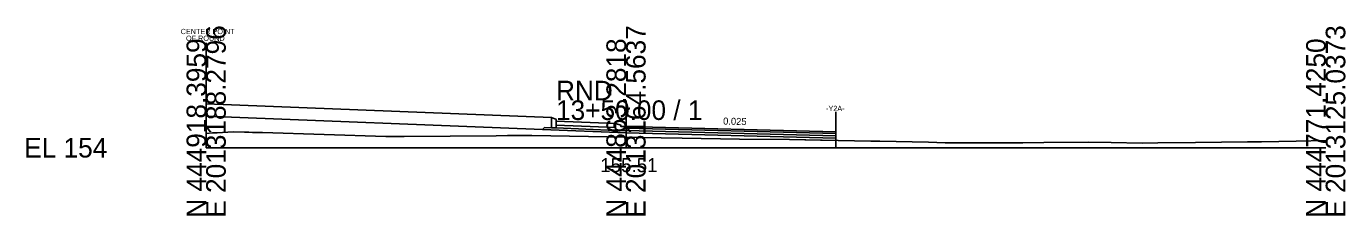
# Model space of a CAD drawing. Extents: x -26 to 163, y -10 to 7518.
# Drawn here: x -25.7 to 162.8, y 6990.3 to 7017.3 of the extents above; entities that cross this region are included whole.
import ezdxf

# ---------------------------------------------------------------- set-up
doc = ezdxf.new("R2010")
doc.units = 0
for name, color, linetype in [('Exist Cross Section Cell', 7, 'Continuous'), ('Exist XS Center Line Elevation Label', 7, 'Continuous'), ('Exist XS Ground Line', 7, 'Continuous'), ('Prop CMT Conc Surface', 7, 'Continuous'), ('Prop CMT Concrete Structures', 7, 'Continuous'), ('Prop CMT Pvmt Course 1', 7, 'Continuous'), ('Prop CMT Pvmt Course 1 CG', 7, 'Continuous'), ('Prop CMT Pvmt Course 2', 7, 'Continuous'), ('Prop CMT Pvmt Course 3', 7, 'Continuous'), ('Prop CMT Pvmt Surface', 7, 'Continuous'), ('Prop CMT Shear Line', 7, 'Continuous'), ('Prop CMT Shear Line Text', 7, 'Continuous'), ('Prop CMT Slope Grass', 7, 'Continuous'), ('Prop CMT Subgrade Earthwork', 7, 'Continuous'), ('Prop XS Earthwork Shape', 7, 'Continuous'), ('Prop XS SE Text', 7, 'Continuous')]:
    doc.layers.add(name, color=color, linetype=linetype)

msp = doc.modelspace()

# ---------------------------------------------------------------- linework, layer by layer
at = {"layer": 'Exist Cross Section Cell'}
for p, q in [((60, 7000), (60, 7006.76)), ((0, 7000), (60, 7000)), ((60, 7000), (160, 7000))]:
    msp.add_line(p, q, dxfattribs=at)
at = {"layer": 'Exist XS Ground Line'}
msp.add_lwpolyline([(0, 7002.05), (0.89, 7002.1), (1.57, 7002.14), (3.85, 7002.25), (5.5, 7002.24), (6.12, 7002.21), (6.63, 7002.19), (7.29, 7002.17), (8.04, 7002.16), (25.69, 7001.61), (26.99, 7001.59), (28.32, 7001.59), (41.46, 7001.71), (43.05, 7001.72), (44.03, 7001.72), (46.53, 7001.73), (60, 7001.51), (62.02, 7001.48), (68.01, 7001.37), (76.24, 7001.24), (83.36, 7001.15), (95.01, 7000.95), (96.27, 7000.92), (103.21, 7000.77), (105.6, 7000.71), (107.14, 7000.68), (111.08, 7000.68), (116.72, 7000.68), (119.69, 7000.72), (126.06, 7000.79), (129.33, 7000.74), (133.77, 7000.66), (136.02, 7000.68), (141.4, 7000.74), (148.82, 7000.83), (150.82, 7000.85), (155.79, 7000.93), (160, 7001.03)], dxfattribs=at)
at = {"layer": 'Prop CMT Conc Surface'}
for points in [[(50, 7003.99), (49.96, 7004.09), (49.85, 7004.14), (49.34, 7004.33)], [(50, 7003.83), (50, 7003.99)], [(60, 7003.03), (59.25, 7003.05), (59.25, 7003.22), (58.5, 7003.47)]]:
    msp.add_lwpolyline(points, dxfattribs=at)
at = {"layer": 'Prop CMT Concrete Structures'}
for points in [[(50, 7003.99), (49.96, 7004.09), (49.85, 7004.14), (49.34, 7004.33)], [(49.34, 7004.33), (49.34, 7002.83)], [(50, 7003.83), (50, 7003.99)], [(49.34, 7002.83), (50, 7002.83)], [(50, 7002.83), (50, 7003.83)], [(50, 7003.83), (50, 7003.24)], [(58.5, 7003.47), (50, 7003.81)], [(50, 7003.22), (58.5, 7002.88)], [(60, 7003.03), (59.25, 7003.05), (59.25, 7003.22), (58.5, 7003.47)], [(58.5, 7003.47), (58.5, 7002.48)], [(58.5, 7002.88), (58.5, 7003.47)], [(58.5, 7002.48), (60, 7002.45)], [(60, 7002.45), (60, 7003.03)]]:
    msp.add_lwpolyline(points, dxfattribs=at)
at = {"layer": 'Prop CMT Pvmt Course 1'}
for points in [[(60, 7003.03), (90, 7002.28)], [(60, 7002.78), (60, 7003.03)], [(90, 7002.03), (60, 7002.78)], [(90, 7002.28), (90, 7002.03)]]:
    msp.add_lwpolyline(points, dxfattribs=at)
msp.add_lwpolyline([(60, 7002.78), (60, 7002.9), (60, 7002.9), (60, 7002.78)], close=True, dxfattribs=at)
at = {"layer": 'Prop CMT Pvmt Course 1 CG'}
for points in [[(60, 7002.11), (60, 7002.45)], [(90, 7001.36), (90, 7001.69)]]:
    msp.add_lwpolyline(points, dxfattribs=at)
at = {"layer": 'Prop CMT Pvmt Course 2'}
for points in [[(60, 7002.45), (60, 7002.78)], [(60, 7002.78), (90, 7002.03)], [(90, 7001.69), (60, 7002.45)], [(90, 7002.03), (90, 7001.69)]]:
    msp.add_lwpolyline(points, dxfattribs=at)
at = {"layer": 'Prop CMT Pvmt Course 3'}
for points in [[(50, 7002.83), (58.5, 7002.48)], [(60, 7002.45), (90, 7001.69)], [(60, 7002.11), (60, 7002.45)], [(90, 7001.36), (60, 7002.11)], [(90, 7001.69), (90, 7001.36)]]:
    msp.add_lwpolyline(points, dxfattribs=at)
at = {"layer": 'Prop CMT Pvmt Surface'}
msp.add_lwpolyline([(60, 7003.03), (90, 7002.28)], dxfattribs=at)
at = {"layer": 'Prop CMT Shear Line'}
for p, q in [((0, 6999.97), (0, 7014.97)), ((90, 7000.1), (90, 7005.12))]:
    msp.add_line(p, q, dxfattribs=at)
at = {"layer": 'Prop CMT Slope Grass'}
for p, q in [((49.34, 7004.31), (0, 7006.28)), ((48.06, 7002.59), (0, 7004.51))]:
    msp.add_line(p, q, dxfattribs=at)
at = {"layer": 'Prop CMT Subgrade Earthwork'}
for p, q in [((0, 7006.28), (0, 7002.05)), ((48.34, 7002.87), (48.06, 7002.59)), ((90, 7002.28), (90, 7001.36)), ((90, 7001.36), (90, 7001.03))]:
    msp.add_line(p, q, dxfattribs=at)
for points in [[(48.06, 7002.59), (60, 7002.11)], [(48.34, 7002.87), (49.34, 7002.83)], [(60, 7002.11), (90, 7001.36)]]:
    msp.add_lwpolyline(points, dxfattribs=at)
at = {"layer": 'Prop XS Earthwork Shape'}
msp.add_lwpolyline([(28.32, 7001.59), (41.46, 7001.71), (43.05, 7001.72), (44.03, 7001.72), (46.53, 7001.73), (60, 7001.51), (62.02, 7001.48), (68.01, 7001.37), (76.24, 7001.24), (83.36, 7001.15), (90, 7001.03), (90, 7001.36), (60, 7002.11), (48.06, 7002.59), (0, 7004.51), (0, 7002.05), (0.89, 7002.1), (1.57, 7002.14), (3.85, 7002.25), (5.5, 7002.24), (6.12, 7002.21), (6.63, 7002.19), (7.29, 7002.17), (8.04, 7002.16), (25.69, 7001.61), (26.99, 7001.59)], close=True, dxfattribs=at)

# ---------------------------------------------------------------- texts
at = {"layer": 'Exist Cross Section Cell'}
for s, p in [('E 2013188.2796', (2.8, 6990)), ('E 2013164.5637', (62.8, 6990)), ('E 2013125.0373', (162.8, 6990)), ('N 444918.3959', (0, 6990)), ('N 444863.2818', (60, 6990)), ('N 444771.4250', (160, 6990))]:
    msp.add_text(s, height=2.8, rotation=90, dxfattribs=at).set_placement(p)
for s, p in [('RND', (50, 7006.76)), ('13+50.00 / 1', (50, 7003.96)), ('EL 154', (-26, 6998.6))]:
    msp.add_text(s, height=2.8, dxfattribs=at).set_placement(p)
at = {"layer": 'Exist XS Center Line Elevation Label'}
msp.add_text('155.51', height=2, dxfattribs=at).set_placement((56.32, 6996.51))
at = {"layer": 'Prop CMT Shear Line Text'}
for s, p in [('CENTER POINT', (-3.64, 7016.22)), ('OF ROUND', (-2.88, 7015.25)), ('-Y2A-', (88.59, 7005.23))]:
    msp.add_text(s, height=0.75, dxfattribs=at).set_placement(p)
at = {"layer": 'Prop XS SE Text'}
msp.add_text('0.025', height=1, rotation=358.5613, dxfattribs=at).set_placement((73.87, 7003.31))

doc.saveas('drawing.dxf')
